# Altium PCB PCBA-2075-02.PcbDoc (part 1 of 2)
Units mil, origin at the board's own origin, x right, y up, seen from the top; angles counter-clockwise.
Board outline 4700 x 3550 mil, 4 copper layers (Top Layer, Signal Layer 1, Signal Layer 2, Bottom Layer), stack 65.3 mil thick; 129 components, 149 nets, 748 pads, 314 vias.
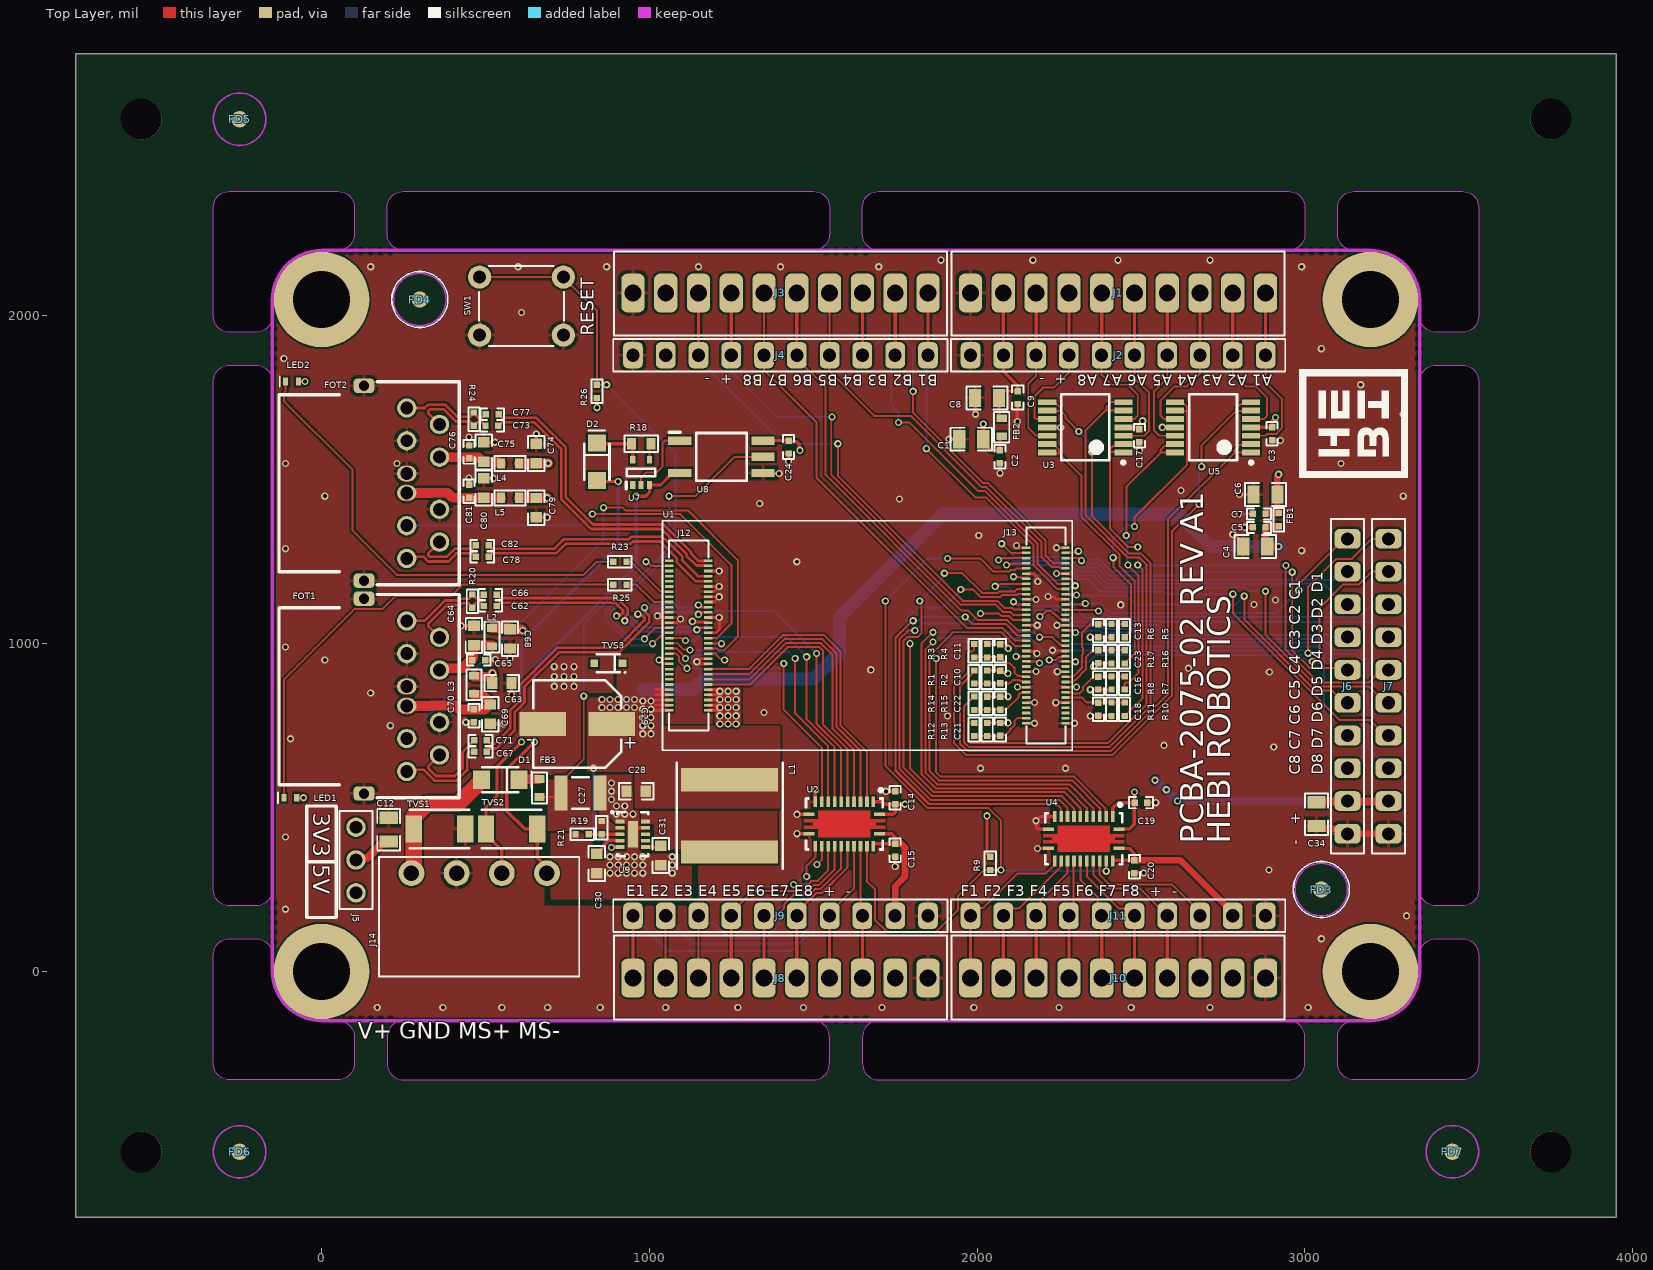
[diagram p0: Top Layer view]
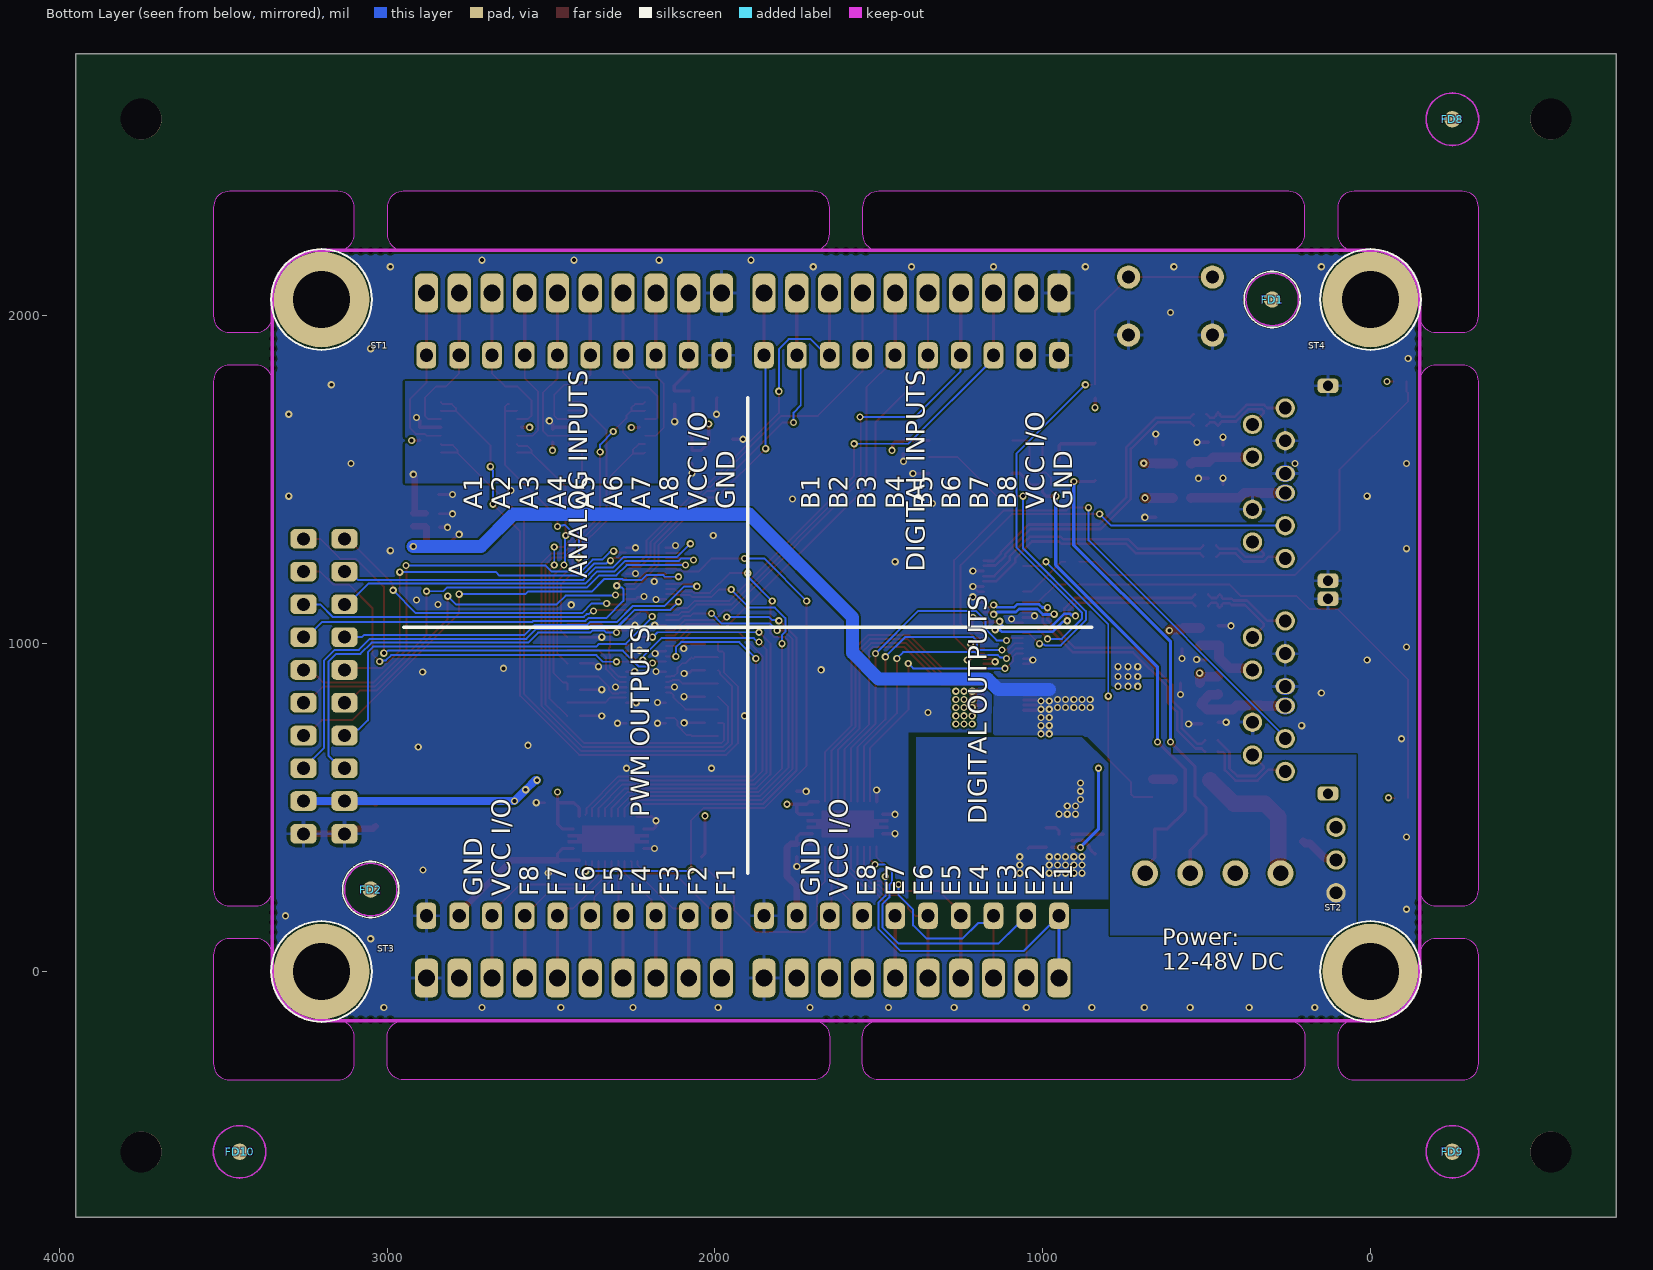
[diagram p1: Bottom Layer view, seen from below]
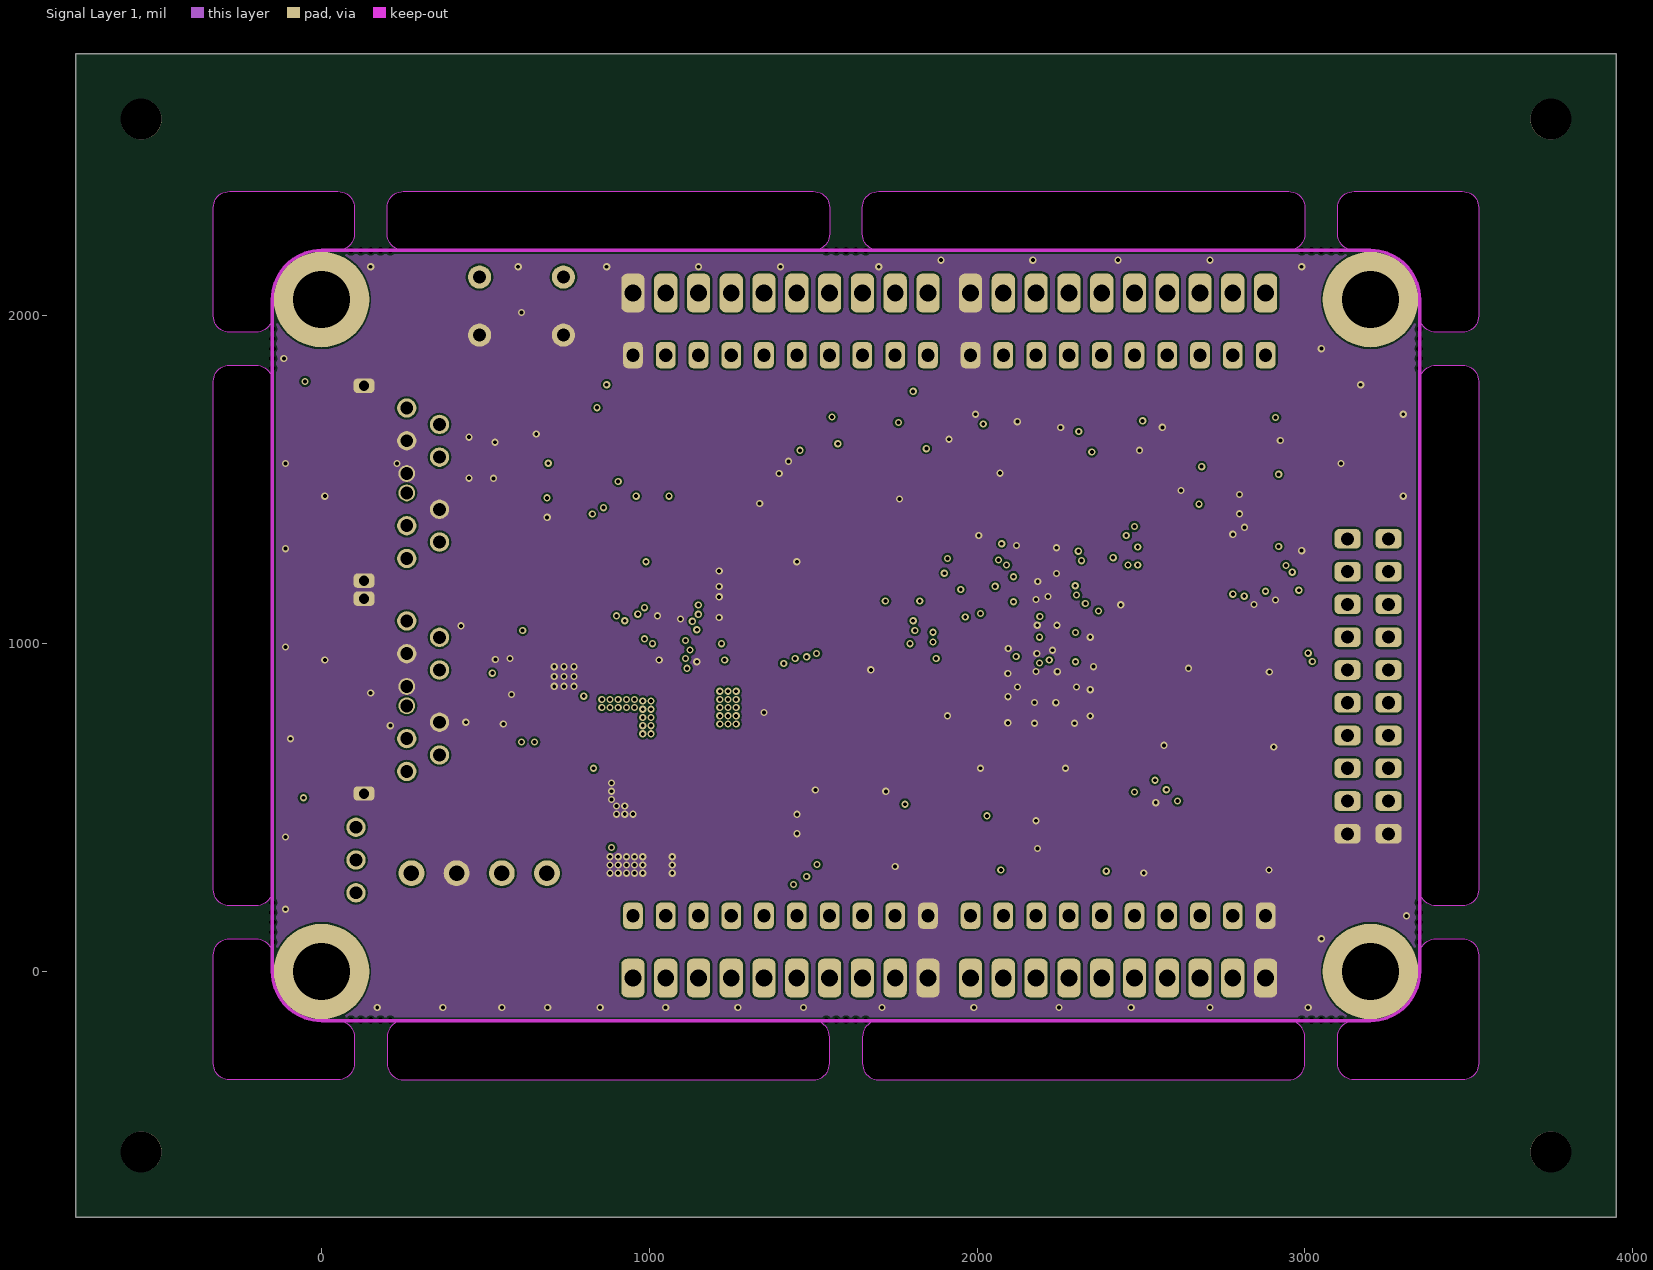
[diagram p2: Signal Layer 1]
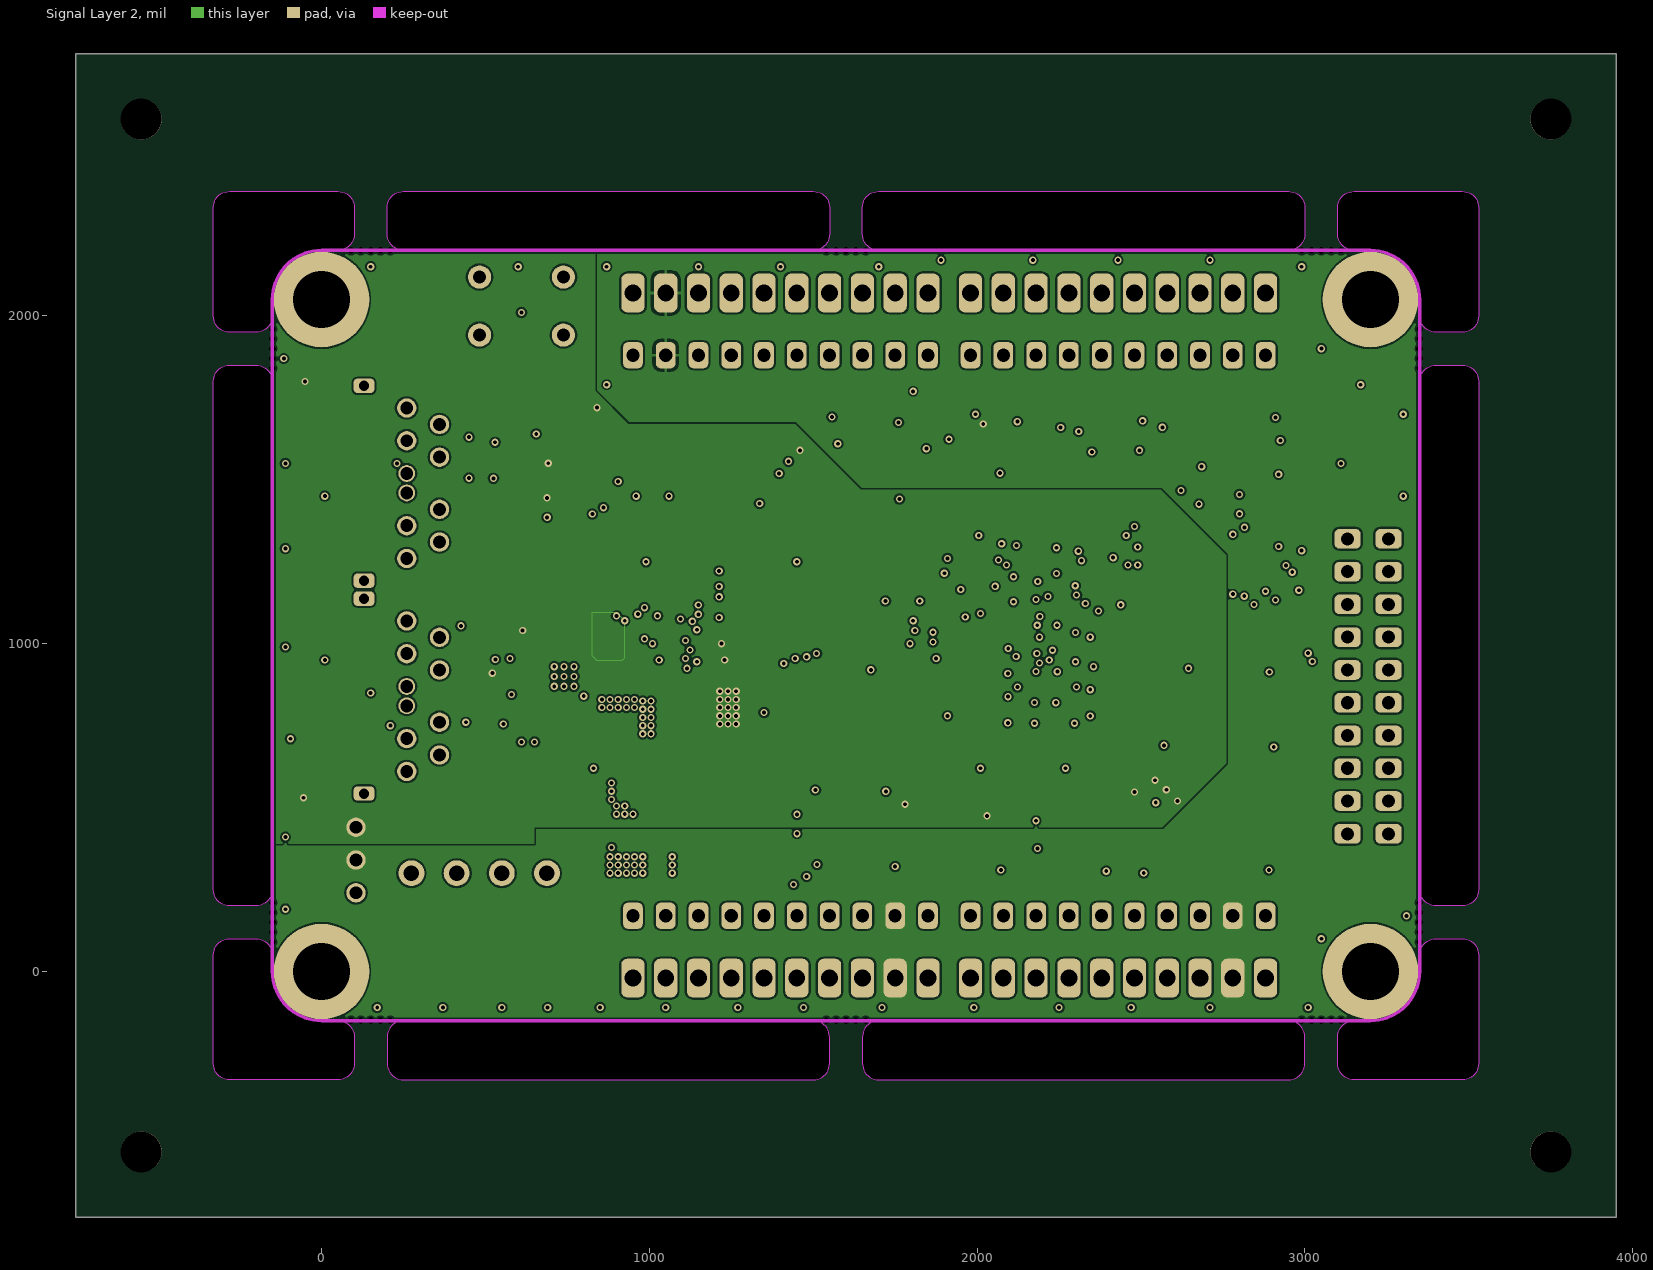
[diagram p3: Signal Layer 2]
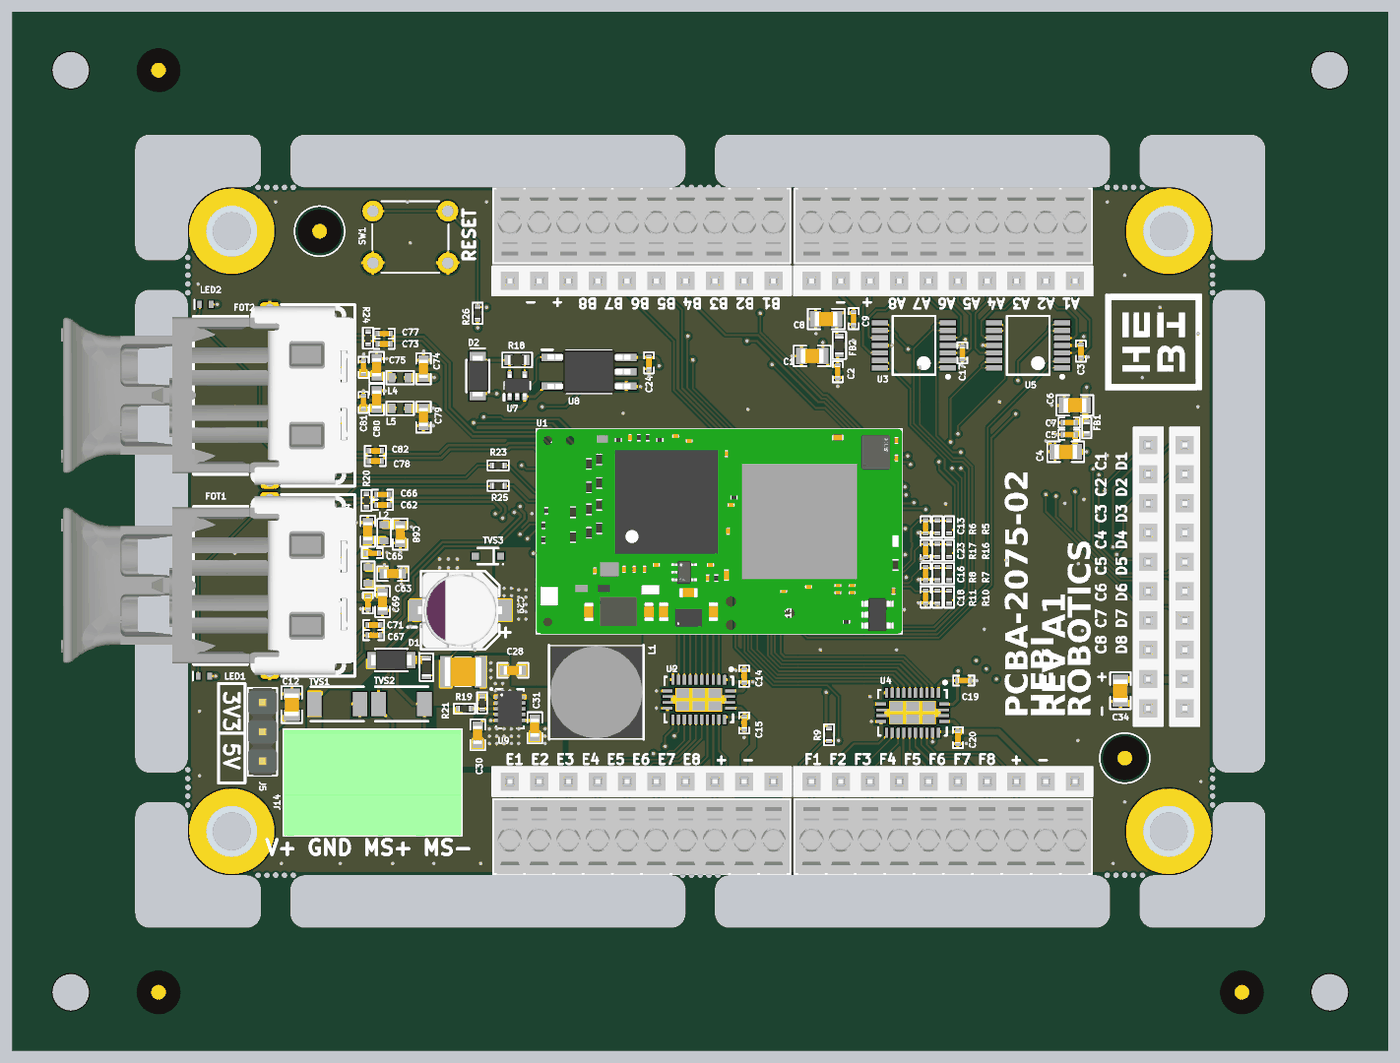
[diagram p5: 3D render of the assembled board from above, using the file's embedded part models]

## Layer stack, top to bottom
Top Solder: solder mask 0.4, Solder Resist, Dk 3.5
Top Layer: signal copper 1.7
Dielectric 1: core 7.9, FR-4, Dk 4.2
Signal Layer 1: signal copper 1.4
Dielectric 4: prepreg 43.3, Dk 4.2
Signal Layer 2: signal copper 1.4
Dielectric 2: core 7.9, Dk 4.2
Bottom Layer: signal copper 1.7
Bottom Solder: solder mask 0.4, Solder Resist, Dk 3.5

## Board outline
-750,-750 3950,-750 3950,2800 -750,2800
cut-out: 3100,-280 3100,-200 cw(c3150,-200) 3150,-150 3200,-150 ccw(c3200,0) 3350,0 3350,50 cw(c3400,50) 3400,100 3480,100 cw(c3480,50) 3530,50 3530,-280 cw(c3480,-280) 3480,-330 3150,-330 cw(c3150,-280)
cut-out: -280,100 -200,100 cw(c-200,50) -150,50 -150,0 ccw(c0,0) 0,-150 50,-150 cw(c50,-200) 100,-200 100,-280 cw(c50,-280) 50,-330 -280,-330 cw(c-280,-280) -330,-280 -330,50 cw(c-280,50)
cut-out: 200,-280 ccw(c250,-280) 250,-330 1500,-330 ccw(c1500,-280) 1550,-280 1550,-200 ccw(c1500,-200) 1500,-150 250,-150 ccw(c250,-200) 200,-200
cut-out: 1650,-280 ccw(c1700,-280) 1700,-330 2950,-330 ccw(c2950,-280) 3000,-280 3000,-200 ccw(c2950,-200) 2950,-150 1700,-150 ccw(c1700,-200) 1650,-200
cut-out: 3350,250 3350,1800 cw(c3400,1800) 3400,1850 3480,1850 cw(c3480,1800) 3530,1800 3530,250 cw(c3480,250) 3480,200 3400,200 cw(c3400,250)
cut-out: 1700,2200 cw(c1700,2250) 1650,2250 1650,2330 cw(c1700,2330) 1700,2380 2950,2380 cw(c2950,2330) 3000,2330 3000,2250 cw(c2950,2250) 2950,2200
cut-out: 200,2250 200,2330 cw(c250,2330) 250,2380 1500,2380 cw(c1500,2330) 1550,2330 1550,2250 cw(c1500,2250) 1500,2200 250,2200 cw(c250,2250)
cut-out: -280,200 cw(c-280,250) -330,250 -330,1800 cw(c-280,1800) -280,1850 -200,1850 cw(c-200,1800) -150,1800 -150,250 cw(c-200,250) -200,200
cut-out: 3480,1950 3400,1950 cw(c3400,2000) 3350,2000 3350,2050 ccw(c3200,2050) 3200,2200 3150,2200 cw(c3150,2250) 3100,2250 3100,2330 cw(c3150,2330) 3150,2380 3480,2380 cw(c3480,2330) 3530,2330 3530,2000 cw(c3480,2000)
cut-out: 100,2330 100,2250 cw(c50,2250) 50,2200 0,2200 ccw(c0,2050) -150,2050 -150,2000 cw(c-200,2000) -200,1950 -280,1950 cw(c-280,2000) -330,2000 -330,2330 cw(c-280,2330) -280,2380 50,2380 cw(c50,2330)

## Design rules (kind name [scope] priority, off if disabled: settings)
Clearance [All] p1: gap=6 ignorepadtopadclearanceinfootprint=FALSE
ComponentClearance ComponentClearance_3 [All vs IsNoBOMComponent] p1: gap=0 collisioncheckmode=3 verticalgap=0 showdistances=FALSE
ComponentClearance ComponentClearance_2 [HasFootprint('ARJM11C7-AB') vs HasFootprint('39-30-1020')] p2: gap=-10000 collisioncheckmode=3 verticalgap=100000 showdistances=FALSE
ComponentClearance ComponentClearance_1 [HasFootprint('ARJM11C7-AB') vs HasFootprint('ARJM11C7-AB')] p3: gap=-10000 collisioncheckmode=3 verticalgap=100000 showdistances=FALSE
ComponentClearance [All] p4: gap=10 collisioncheckmode=3 verticalgap=10 showdistances=FALSE
DiffPairsRouting [All] p1: maxlimit=10 minlimit=6 mostfreqgap=6 toplayer_minwidth=8 toplayer_maxwidth=15 toplayer_prefwidth=8 midlayer1_minwidth=8 midlayer1_maxwidth=15 midlayer1_prefwidth=8 midlayer2_minwidth=8 midlayer2_maxwidth=15 midlayer2_prefwidth=8 bottomlayer_minwidth=8 bottomlayer_maxwidth=15 bottomlayer_prefwidth=8 substack1={6BA4272A-E36A-4244-B1C5-CEF2182E9F2F} toplayer_{6ba4272a-e36a-4244-b1c5-cef2182e9f2f}_minwidth=15 toplayer_{6ba4272a-e36a-4244-b1c5-cef2182e9f2f}_maxwidth=15 toplayer_{6ba4272a-e36a-4244-b1c5-cef2182e9f2f}_prefwidth=15 midlayer1_{6ba4272a-e36a-4244-b1c5-cef2182e9f2f}_minwidth=15 midlayer1_{6ba4272a-e36a-4244-b1c5-cef2182e9f2f}_maxwidth=15 midlayer1_{6ba4272a-e36a-4244-b1c5-cef2182e9f2f}_prefwidth=15 midlayer2_{6ba4272a-e36a-4244-b1c5-cef2182e9f2f}_minwidth=15 midlayer2_{6ba4272a-e36a-4244-b1c5-cef2182e9f2f}_maxwidth=15 midlayer2_{6ba4272a-e36a-4244-b1c5-cef2182e9f2f}_prefwidth=15 bottomlayer_{6ba4272a-e36a-4244-b1c5-cef2182e9f2f}_minwidth=15 bottomlayer_{6ba4272a-e36a-4244-b1c5-cef2182e9f2f}_maxwidth=15 bottomlayer_{6ba4272a-e36a-4244-b1c5-cef2182e9f2f}_prefwidth=15 substack2={BF52BF6C-AB74-4071-B511-A36AC5A0F64E} toplayer_{bf52bf6c-ab74-4071-b511-a36ac5a0f64e}_minwidth=15 toplayer_{bf52bf6c-ab74-4071-b511-a36ac5a0f64e}_maxwidth=15 toplayer_{bf52bf6c-ab74-4071-b511-a36ac5a0f64e}_prefwidth=15 midlayer1_{bf52bf6c-ab74-4071-b511-a36ac5a0f64e}_minwidth=15 midlayer1_{bf52bf6c-ab74-4071-b511-a36ac5a0f64e}_maxwidth=15 midlayer1_{bf52bf6c-ab74-4071-b511-a36ac5a0f64e}_prefwidth=15 midlayer2_{bf52bf6c-ab74-4071-b511-a36ac5a0f64e}_minwidth=15 midlayer2_{bf52bf6c-ab74-4071-b511-a36ac5a0f64e}_maxwidth=15 midlayer2_{bf52bf6c-ab74-4071-b511-a36ac5a0f64e}_prefwidth=15 bottomlayer_{bf52bf6c-ab74-4071-b511-a36ac5a0f64e}_minwidth=15 bottomlayer_{bf52bf6c-ab74-4071-b511-a36ac5a0f64e}_maxwidth=15 bottomlayer_{bf52bf6c-ab74-4071-b511-a36ac5a0f64e}_prefwidth=15 substack3={B0BE1522-C43A-4A1D-8C74-4FD47ECCD6AD} toplayer_{b0be1522-c43a-4a1d-8c74-4fd47eccd6ad}_minwidth=15 toplayer_{b0be1522-c43a-4a1d-8c74-4fd47eccd6ad}_maxwidth=15 toplayer_{b0be1522-c43a-4a1d-8c74-4fd47eccd6ad}_prefwidth=15 midlayer1_{b0be1522-c43a-4a1d-8c74-4fd47eccd6ad}_minwidth=15 midlayer1_{b0be1522-c43a-4a1d-8c74-4fd47eccd6ad}_maxwidth=15 midlayer1_{b0be1522-c43a-4a1d-8c74-4fd47eccd6ad}_prefwidth=15 midlayer2_{b0be1522-c43a-4a1d-8c74-4fd47eccd6ad}_minwidth=15 midlayer2_{b0be1522-c43a-4a1d-8c74-4fd47eccd6ad}_maxwidth=15 midlayer2_{b0be1522-c43a-4a1d-8c74-4fd47eccd6ad}_prefwidth=15 bottomlayer_{b0be1522-c43a-4a1d-8c74-4fd47eccd6ad}_minwidth=15 bottomlayer_{b0be1522-c43a-4a1d-8c74-4fd47eccd6ad}_maxwidth=15 bottomlayer_{b0be1522-c43a-4a1d-8c74-4fd47eccd6ad}_prefwidth=15 maxuncoupledlength=500
Height [All] p1: minheight=0 maxheight=2000 prefheight=500
HoleSize [All] p1: absolutevalues=TRUE maxlimit=1000 minlimit=1 maxpercent=80.000 minpercent=20.000
HoleToHoleClearance HoleToHoleClearance_1 [HasFootprint('PJ-037A') vs HasFootprint('PJ-037A')] p1: gap=0 allowstackedmicrovias=TRUE
HoleToHoleClearance [All] p2: gap=10 allowstackedmicrovias=TRUE
MinimumSolderMaskSliver [All] p1 off: minsoldermaskwidth=10
PolygonConnect PolygonConnect_1 [All vs IsNamedPolygon('NO_THERMAL')] p1: connectstyle=Direct reliefconductorwidth=10 reliefentries=4 polygonreliefangle="90 Angle" airgapwidth=10
PolygonConnect [All] p2: thpad.connectstyle=Relief thpad.reliefconductorwidth=10 thpad.reliefentries=4 thpad.polygonreliefangle="90 Angle" thpad.airgapwidth=10 smdpad.connectstyle=Relief smdpad.reliefconductorwidth=10 smdpad.reliefentries=4 smdpad.polygonreliefangle="90 Angle" smdpad.airgapwidth=10 via.connectstyle=Direct via.reliefconductorwidth=10 via.reliefentries=4 via.polygonreliefangle="90 Angle" via.airgapwidth=10
RoutingVias [All] p1: holewidth=12 width=22 viastyle="Through Hole" minholewidth=12 minwidth=22 maxholewidth=40 maxwidth=100
SilkToSilkClearance [All] p1 off: silktosilkclearance=10
SilkToSolderMaskClearance [IsPad] p1 off: minsilkscreentomaskgap=10 clearancetoexposedcopper=TRUE
SolderMaskExpansion "Via Tenting" [IsVia] p1: expansion=2 istentingtop=TRUE
SolderMaskExpansion SolderMaskExpansion_1 [All] p2: expansion=4 istentingtop=FALSE
Width [All] p1: maxlimit=200 minlimit=6 preferedwidth=6 substack1={6BA4272A-E36A-4244-B1C5-CEF2182E9F2F} substack2={BF52BF6C-AB74-4071-B511-A36AC5A0F64E} substack3={B0BE1522-C43A-4A1D-8C74-4FD47ECCD6AD}
22 further rules are at their usual default settings.

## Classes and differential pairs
component class PCBA-2075-02: C24 C27 C28 C29 C30 C31 C62 C63 C64 C65 C66 C67 C68 C69 C70 C71 C73 C74 C75 C76 C77 C78 C79 C80 C81 C82 D1 D2 FB3 FD1 FD2 FD3 FD4 FD5 FD6 FD7 FD8 FD9 FD10 FOT1 FOT2 J12 J13 J14 L1 L2 L3 L4 L5 LED1 LED2 R18 R19 R20 R21 R23 R24 R25 R26 ST1 ST2 ST3 ST4 SW1 TVS1 TVS2 TVS3 U5 U7 U8 U9
component class io_connectors: C1 C2 C3 C4 C5 C6 C7 C8 C9 C10 C11 C12 C13 C14 C15 C16 C17 C18 C19 C20 C21 C22 C23 C34 FB1 FB2 J1 J2 J3 J4 J5 J6 J7 J8 J9 J10 J11 R1 R2 R3 R4 R5 R6 R7 R8 R9 R10 R11 R12 R13 R14 R15 R16 R17 U2 U3 U4 U5
differential pair TX2A: +TX2A_P -TX2A_N
differential pair TX1A: +TX1A_P -TX1A_N
differential pair RX2A: +RX2A_P -RX2A_N
differential pair RX1A: +RX1A_P -RX1A_N
differential pair TX2: +TX2_P -TX2_N
differential pair TX1: +TX1_P -TX1_N
differential pair RX2: +RX2_P -RX2_N
differential pair RX1: +RX1_P -RX1_N

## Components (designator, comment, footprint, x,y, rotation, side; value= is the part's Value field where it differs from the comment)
C1 "C-10uf-X5R-25V-10%-0805" C0805 1982.28,1623.79 r0 top
C2 "C-0.1uf-X7R-25V-10%-0402" C0402 2069.69,1570 r270 top
C3 "C-0.1uf-X7R-25V-10%-0402" C0402 2900,1640 r270 top
C4 "C-10uf-X5R-25V-10%-0805" C0805 2848.58,1296.61 r0 top
C5 "C-0.1uf-X7R-25V-10%-0402" C0402 2860,1355 r180 top
C6 "C-10uf-X5R-25V-10%-0805" C0805 2879.69,1455 r0 top
C7 "C-0.1uf-X7R-25V-10%-0402" C0402 2860,1396.17 r180 top
C8 "C-10uf-X5R-25V-10%-0805" C0805 2030,1750 r0 top
C9 "C-0.1uf-X7R-25V-10%-0402" C0402 2124,1751 r90 top
C10 "C-10000pf-X7R-50V-10%-0402" C0402 2070.63,898.39 r270 top
C11 "C-10000pf-X7R-50V-10%-0402" C0402 2070.63,978.39 r270 top
C12 "C-10uf-X5R-25V-10%-0805" C0805 205,432.72 r270 top
C13 "C-10000pf-X7R-50V-10%-0402" C0402 2370,1040 r90 top
C14 "C-0.1uf-X7R-25V-10%-0402" C0402 1750,530 r270 top
C15 "C-0.1uf-X7R-25V-10%-0402" C0402 1750,370 r90 top
C16 "C-10000pf-X7R-50V-10%-0402" C0402 2370,880 r90 top
C17 "C-0.1uf-X7R-25V-10%-0402" C0402 2495,1634.41 r270 top
C18 "C-10000pf-X7R-50V-10%-0402" C0402 2370,800 r90 top
C19 "C-0.1uf-X7R-25V-10%-0402" C0402 2500,515 r180 top
C20 "C-0.1uf-X7R-25V-10%-0402" C0402 2480,320 r90 top
C21 "C-10000pf-X7R-50V-10%-0402" C0402 2070.63,738.39 r270 top
C22 "C-10000pf-X7R-50V-10%-0402" C0402 2070.63,818.39 r270 top
C23 "C-10000pf-X7R-50V-10%-0402" C0402 2370,960 r90 top
C24 "CMP-00040-11" C0402 1425,1600 r270 top
C27 "C-4.7uf-X7S-100V-20%-1210" C1210 790,545 r180 top
C28 "C-10uf-X5R-16V-10%-0603" C0603 960,550 r0 top
C29 "16SVPC100M" CAPAE127P600-8N 780,755 r180 top locked
C30 "C-1uf-X7R-25V-10%-0603" C0603 840,329.53 r270 top
C31 "C-1uf-X7R-25V-10%-0603" C0603 1035,353.73 r270 top
C34 "C-10uf-X5R-25V-10%-0805" C0805 3035,480 r90 top
C62 "CMP-00040-11" C0402 515,1115 r180 top
C63 "C-10uf-X5R-16V-10%-0603" C0603 550,880 r180 top
C64 "C-10uf-X5R-16V-10%-0603" C0603 465,1025 r270 top
C65 "CMP-00040-11" C0402 480,950 r180 top
C66 "CMP-00040-11" C0402 515,1150 r180 top
C67 "CMP-00040-11" C0402 485,670 r180 top
C68 "C-10uf-X5R-16V-10%-0603" C0603 575,1015 r90 top
C69 "C-10uf-X5R-16V-10%-0603" C0603 515,785 r90 top
C70 "CMP-00040-11" C0402 465,780 r270 top
C71 "CMP-00040-11" C0402 485,705 r180 top
C73 "CMP-00040-11" C0402 520,1665 r0 top
C74 "C-10uf-X5R-16V-10%-0603" C0603 655,1580 r270 top
C75 "C-10uf-X5R-16V-10%-0603" C0603 495,1585 r270 top
C76 "CMP-00040-11" C0402 450,1585 r270 top
C77 "CMP-00040-11" C0402 520.31,1700 r0 top
C78 "CMP-00040-11" C0402 490,1265 r0 top
C79 "C-10uf-X5R-16V-10%-0603" C0603 655,1415 r90 top
C80 "C-10uf-X5R-16V-10%-0603" C0603 495,1475 r270 top
C81 "CMP-00040-11" C0402 450,1465 r90 top
C82 "CMP-00040-11" C0402 490.31,1300 r0 top
D1 "STPS2H100ZFY" SOD123F_ST 545,585 r180 top
D2 "STPS2H100ZFY" SOD123F_ST 840,1555 r270 top
FB1 "MMZ1005A222ET000" FB0402 2920,1378.35 r90 top
FB2 "MPZ1608S331ATD25" FB0603 2075,1660.18 r90 top
FB3 "MPZ1608S331ATD25" FB0603 665,560 r270 top
FD1 "FIDUCIAL" fiducial_01 300,2050 r180 bottom
FD2 "FIDUCIAL" fiducial_01 3050,250 r180 bottom
FD3 "FIDUCIAL" fiducial_01 3050,250 r0 top
FD4 "FIDUCIAL" fiducial_01 300,2050 r0 top
FD5 "*" fiducial_01_no_overlay -250,2600 r0 top
FD6 "*" fiducial_01_no_overlay -250,-550 r0 top
FD7 "*" fiducial_01_no_overlay 3450,-550 r0 top
FD8 "*" fiducial_01_no_overlay -250,2600 r180 bottom
FD9 "*" fiducial_01_no_overlay -250,-550 r180 bottom
FD10 "*" fiducial_01_no_overlay 3450,-550 r180 bottom
FOT1 "FB2M5KVR" OPTOLOCK 260,840 r180 top locked
FOT2 "FB2M5KVR" OPTOLOCK 260,1489.53 r180 top locked
J1 "OSTVN10A150" OSTVN10A150 2430,2070 r180 top locked
J2 "PPTC101LFBN-RC" PPTC101LFBN-RC 2430,1880 r180 top locked
J3 "OSTVN10A150" OSTVN10A150 1400,2070 r180 top locked
J4 "PPTC101LFBN-RC" PPTC101LFBN-RC 1400,1880 r180 top locked
J5 "M20-9990345" M20-9990345 105,340 r90 top
J6 "PPTC101LFBN-RC" PPTC101LFBN-RC 3130,870 r270 top
J7 "PPTC101LFBN-RC" PPTC101LFBN-RC 3255,870 r270 top
J8 "OSTVN10A150" OSTVN10A150 1400,-20 r0 top locked
J9 "PPTC101LFBN-RC" PPTC101LFBN-RC 1400,170 r0 top locked
J10 "OSTVN10A150" OSTVN10A150 2430,-20 r0 top locked
J11 "PPTC101LFBN-RC" PPTC101LFBN-RC 2430,170 r0 top locked
J12 "DF40HC(3.0)-60DS-0.4V(51)" DF40HC(3.0)-60DS-0.4V(51) 1120,1025 r90 top locked
J13 "DF40HC(3.0)-70DS-0.4V(51)" DF40HC(3.0)-70DS-0.4V(51) 2210,1025 r90 top locked
J14 "1844236" 1844236 481.1,300 r0 top locked
L1 "NRS8040T220MJGJV" NR8040T220M 1245,475 r90 top
L2 "ASMPH-0603-1R0M-T" I0603 520,1020 r270 top
L3 "ASMPH-0603-1R0M-T" I0603 465,875 r270 top
L4 "ASMPH-0603-1R0M-T" I0603 575,1550 r180 top
L5 "ASMPH-0603-1R0M-T" I0603 575,1445 r180 top
LED1 "IN-S42ATG" IN-S42AT -95,530 r180 top
LED2 "IN-S42ATG" IN-S42AT -90,1800 r180 top
R1 "R-3.3k-0.1%-0.063w-0402" R0402 1990.63,898.39 r270 top
R2 "R-4.7k-0.1%-0.063w-0402" R0402 2030.63,898.39 r270 top
R3 "R-3.3k-0.1%-0.063w-0402" R0402 1990.63,978.39 r270 top
R4 "R-4.7k-0.1%-0.063w-0402" R0402 2030.63,978.39 r270 top
R5 "R-3.3k-0.1%-0.063w-0402" R0402 2450,1040 r90 top
R6 "R-4.7k-0.1%-0.063w-0402" R0402 2410,1040 r90 top
R7 "R-3.3k-0.1%-0.063w-0402" R0402 2450,880 r90 top
R8 "R-4.7k-0.1%-0.063w-0402" R0402 2410,880 r90 top
R9 "R-4.7k-1%-0.063w-0402" R0402 2040,330 r270 top
R10 "R-3.3k-0.1%-0.063w-0402" R0402 2450,800 r90 top
R11 "R-4.7k-0.1%-0.063w-0402" R0402 2410,800 r90 top
R12 "R-3.3k-0.1%-0.063w-0402" R0402 1990.63,738.39 r270 top
R13 "R-4.7k-0.1%-0.063w-0402" R0402 2030.63,738.39 r270 top
R14 "R-3.3k-0.1%-0.063w-0402" R0402 1990.63,818.39 r270 top
R15 "R-4.7k-0.1%-0.063w-0402" R0402 2030.63,818.21 r270 top
R16 "R-3.3k-0.1%-0.063w-0402" R0402 2450,960 r90 top
R17 "R-4.7k-0.1%-0.063w-0402" R0402 2410,960 r90 top
R18 "R-220-1%-0.25w-0603" R0603 975,1610 r180 top
R19 "R-3.3M-1%-0.063w-0402" R0402 855,438.73 r90 top
R20 "R-100-1%-0.063w-0402" R0402 460,1130 r90 top value=100
R21 "R-470k-1%-0.063w-0402" R0402 795,418.73 r180 top
R23 "R-1k-1%-0.063w-0402" R0402 910,1250 r180 top
R24 "R-100-1%-0.063w-0402" R0402 465,1685 r90 top value=100
R25 "R-1k-1%-0.063w-0402" R0402 910,1180 r180 top
R26 "R-10k-1%-0.063w-0402" R0402 840,1770 r270 top
ST1 "9774030960R" 9774030960R 3200,2050 r180 bottom locked
ST2 "9774030960R" 9774030960R 0,0 r180 bottom locked
ST3 "9774030960R" 9774030960R 3200,0 r180 bottom locked
ST4 "9774030960R" 9774030960R 0,2050 r180 bottom locked
SW1 "222ADVBA" 222ADVBA 610,2030 r0 top locked
TVS1 "SMAJ51CA" SMA_BI_BOURNS 360,435 r0 top
TVS2 "SMAJ51CA" SMA_BI_BOURNS 580,435 r0 top
TVS3 "PESD5V0S1UJ,115" SOD-323F_NXP 875,940 r180 top
U1 "IO-MICRO" IO-MICRO-Footprint-1 1665,1025 r0 top
U2 "SN74LVC8T245RHLR" R-PVQFN-N24_TI 1595,450 r270 top
U3 "TSV324IPT" TSSOP14_ST 2330,1660 r180 top
U4 "SN74LVC8T245RHLR" R-PVQFN-N24_TI 2325,405 r270 top
U5 "TSV324IPT" TSSOP14_ST 2720,1660 r180 top
U7 "PSSI2021SAY,115" PSSI2021SAY,115 975,1522.5 r90 top
U8 "ACPL-M21L-500E" SOT125P700X260-5N 1220,1570 r0 top
U9 "MAX17502FATB+T" 10_TDFN_MAXIM 950,418.73 r0 top

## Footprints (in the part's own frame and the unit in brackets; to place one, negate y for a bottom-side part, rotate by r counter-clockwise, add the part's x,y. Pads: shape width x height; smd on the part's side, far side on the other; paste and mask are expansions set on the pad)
10_TDFN_MAXIM [mm] "10 TDFN from Maxim MAX17502"
  rect 0.7x0.3 smd: 1(-0.99,1) 2(-0.99,0.5) 3(-0.99,0) 4(-0.99,-0.5) 5(-0.99,-1) 6(0.99,-1) 7(0.99,-0.5) 8(0.99,0) 9(0.99,0.5) 10(0.99,1)
  rect 0.8x2.08 smd: 11(0,0)
  silkscreen extent -1.65,-1.7 1.2,1.75, body extent -1.05,-1.55 1.05,1.55, height 0.8
222ADVBA [mm] "222ADVBA from CTS"
  round 1.8 hole 1: 1(-3.25,2.25) 1(3.25,2.25) 2(-3.25,-2.25) 2(3.25,-2.25)
  silkscreen extent -3.3,-3.1 3.3,3.1, body extent -3.25,-3 3.25,3, height 4.3
1844236 [mm] "TERM BLOCK HDR 4POS 90DEG 3.5MM, Pheonix Contact"
  round 2 hole 1.2: 1(-5.25,0) 2(-1.75,0) 3(1.75,0) 4(5.25,0)
  silkscreen extent -7.75,-8 7.75,1.25, body extent -7.7,-8 7.7,1.2, height 7.25
9774030960R [mm] "3mm SMD Spacer from Wurth"
  round 7.4 hole 4.4: 1(0,0)
  silkscreen extent -3.9,-3.9 3.9,3.9, body extent -3,-3 2.99,3, height 2.03
C0402 [mm] "Generic 0402 Capacitor"
  rect 0.5x0.5 smd: 1(-0.5,0) 2(0.5,0)
  silkscreen extent -0.91,-0.43 0.91,0.43, body extent -0.5,-0.25 0.5,0.25, height 0.55
C0603 [mm] "Generic 0603 Capacitor"
  rect 0.8x0.9 smd: 1(-0.75,0) 2(0.75,0)
  silkscreen extent -1.35,-0.64 1.35,0.64, body extent -0.8,-0.4 0.8,0.4, height 0.9
C0805 [mm] "Generic 0805 Capacitor"
  rect 0.95x1.4 smd: 1(-0.925,0) 2(0.925,0)
  silkscreen extent -1.6,-0.89 1.6,0.89, body extent -1,-0.63 1,0.63, height 1.4
C1210 [mm] "Generic 1210 capacitor"
  rect 1x2.7 smd: 1(-1.5,0) 2(1.5,0)
  silkscreen extent -0.65,-1.22 0.65,1.23, body extent -1.6,-1.25 1.6,1.25, height 2.8
CAPAE127P600-8N [mm]
  rect 3.6x1.85 smd: +(-2.675,0) -(2.675,0)
  silkscreen extent -3.4,-3.4 3.4,3.4, body extent -3.65,-3.3 3.65,3.3, height 5.94
DF40HC(3.0)-60DS-0.4V(51) [mm] "DF40HC(3.0)-60DS-0.4V(51)"
  rect 0.203x0.65 smd paste+0 mask+0: 1(5.8,-1.515) 2(5.8,1.515) 3(5.4,-1.515) 4(5.4,1.515) 5(5,-1.515) 6(5,1.515) 7(4.6,-1.515) 8(4.6,1.515) 9(4.2,-1.515) 10(4.2,1.515) 11(3.8,-1.515) 12(3.8,1.515) 13(3.4,-1.515) 14(3.4,1.515) 15(3,-1.515) 16(3,1.515) 17(2.6,-1.515) 18(2.6,1.515) 19(2.2,-1.515) 20(2.2,1.515) 21(1.8,-1.515) 22(1.8,1.515) 23(1.4,-1.515) 24(1.4,1.515) 25(1,-1.515) 26(1,1.515) 27(0.6,-1.515) 28(0.6,1.515) 29(0.2,-1.515) 30(0.2,1.515) 31(-0.2,-1.515) 32(-0.2,1.515) 33(-0.6,-1.515) 34(-0.6,1.515) 35(-1,-1.515) 36(-1,1.515) 37(-1.4,-1.515) 38(-1.4,1.515) 39(-1.8,-1.515) 40(-1.8,1.515) 41(-2.2,-1.515) 42(-2.2,1.515) 43(-2.6,-1.515) 44(-2.6,1.515) 45(-3,-1.515) 46(-3,1.515) 47(-3.4,-1.515) 48(-3.4,1.515) 49(-3.8,-1.515) 50(-3.8,1.515) 51(-4.2,-1.515) 52(-4.2,1.515) 53(-4.6,-1.515) 54(-4.6,1.515) 55(-5,-1.515) 56(-5,1.515) 57(-5.4,-1.515) 58(-5.4,1.515) 59(-5.8,-1.515) 60(-5.8,1.515)
  silkscreen extent -7.38,-1.52 7.38,1.52, body extent -7.3,-1.69 7.3,1.69, height 2.9
DF40HC(3.0)-70DS-0.4V(51) [mm] "3mm height DF40, 70pin Hirose"
  rect 0.203x0.65 smd paste+0 mask+0: 1(6.8,-1.515) 2(6.8,1.515) 3(6.4,-1.515) 4(6.4,1.515) 5(6,-1.515) 6(6,1.515) 7(5.6,-1.515) 8(5.6,1.515) 9(5.2,-1.515) 10(5.2,1.515) 11(4.8,-1.515) 12(4.8,1.515) 13(4.4,-1.515) 14(4.4,1.515) 15(4,-1.515) 16(4,1.515) 17(3.6,-1.515) 18(3.6,1.515) 19(3.2,-1.515) 20(3.2,1.515) 21(2.8,-1.515) 22(2.8,1.515) 23(2.4,-1.515) 24(2.4,1.515) 25(2,-1.515) 26(2,1.515) 27(1.6,-1.515) 28(1.6,1.515) 29(1.2,-1.515) 30(1.2,1.515) 31(0.8,-1.515) 32(0.8,1.515) 33(0.4,-1.515) 34(0.4,1.515) 35(0,-1.515) 36(0,1.515) 37(-0.4,-1.515) 38(-0.4,1.515) 39(-0.8,-1.515) 40(-0.8,1.515) 41(-1.2,-1.515) 42(-1.2,1.515) 43(-1.6,-1.515) 44(-1.6,1.515) 45(-2,-1.515) 46(-2,1.515) 47(-2.4,-1.515) 48(-2.4,1.515) 49(-2.8,-1.515) 50(-2.8,1.515) 51(-3.2,-1.515) 52(-3.2,1.515) 53(-3.6,-1.515) 54(-3.6,1.515) 55(-4,-1.515) 56(-4,1.515) 57(-4.4,-1.515) 58(-4.4,1.515) 59(-4.8,-1.515) 60(-4.8,1.515) 61(-5.2,-1.515) 62(-5.2,1.515) 63(-5.6,-1.515) 64(-5.6,1.515) 65(-6,-1.515) 66(-6,1.515) 67(-6.4,-1.515) 68(-6.4,1.515) 69(-6.8,-1.515) 70(-6.8,1.515)
  silkscreen extent -8.38,-1.52 8.38,1.52, body extent -8.3,-1.69 8.3,1.69, height 2.9
FB0402 [mm] "Chip Ferrite Bead 2-Leads, Body 1.0x0.5mm, based on Panasonic datasheet"
  rect 0.475x0.5 smd: 1(-0.513,0) 2(0.512,0)
  silkscreen extent -0.9,-0.4 0.9,0.4, body extent -0.5,-0.28 0.5,0.28, height 0.55
FB0603 [mm] "Based on TDK datasheet for MMZ Series"
  rect 0.6x0.8 smd: 1(-0.7,0) 2(0.7,0)
  silkscreen extent -1.19,-0.58 1.19,0.58, body extent -0.8,-0.4 0.8,0.4, height 0.8
fiducial_01 [mil] "fiducial"
  round 50 smd paste-100 mask+50: F(0,0)
  Top Layer keep-out circle w5: c0,0 r80
  silkscreen extent -86,-85 86,85
fiducial_01_no_overlay [mil] "fiducial"
  round 50 smd paste-100 mask+50: F(0,0)
  Top Layer keep-out circle w5: c0,0 r80
I0603 [mm] "Based on TDK datasheet for MMZ Series"
  rect 0.6x0.8 smd: 1(-0.7,0) 2(0.7,0)
  silkscreen extent -1.19,-0.58 1.19,0.58, body extent -0.88,-0.48 0.87,0.48, height 0.95
IN-S42AT [mm] "single 0402 LED 0.35mm height based on IN-S42AT"
  rect 0.4x0.6 smd: A(-0.5,0) C(0.5,0)
  silkscreen extent 0.95,-0.4 0.95,0.4, body extent -0.5,-0.25 0.5,0.25, height 0.35
IO-MICRO-Footprint-1 [mil]
  rect 4x4 smd paste-1000 mask+0: A1(604.65,267.72) A2(485.35,267.72) A3(604.65,251.97) A4(485.35,251.97) A5(604.65,236.22) A6(485.35,236.22) A7(604.65,220.47) A8(485.35,220.47) A9(604.65,204.72) A10(485.35,204.72) A11(604.65,188.98) A12(485.35,188.98) A13(604.65,173.23) A14(485.35,173.23) A15(604.65,157.48) A16(485.35,157.48) A17(604.65,141.73) A18(485.35,141.73) A19(604.65,125.98) A20(485.35,125.98) A21(604.65,110.24) A22(485.35,110.24) A23(604.65,94.49) A24(485.35,94.49) A25(604.65,78.74) A26(485.35,78.74) A27(604.65,62.99) A28(485.35,62.99) A29(604.65,47.24) A30(485.35,47.24) A31(604.65,31.5) A32(485.35,31.5) A33(604.65,15.75) A34(485.35,15.75) A35(604.65,0) A36(485.35,0) A37(604.65,-15.75) A38(485.35,-15.75) A39(604.65,-31.5) A40(485.35,-31.5) A41(604.65,-47.24) A42(485.35,-47.24) A43(604.65,-62.99) A44(485.35,-62.99) A45(604.65,-78.74) A46(485.35,-78.74) A47(604.65,-94.49) A48(485.35,-94.49) A49(604.65,-110.24) A50(485.35,-110.24) A51(604.65,-125.98) A52(485.35,-125.98) A53(604.65,-141.73) A54(485.35,-141.73) A55(604.65,-157.48) A56(485.35,-157.48) A57(604.65,-173.23) A58(485.35,-173.23) A59(604.65,-188.98) A60(485.35,-188.98) A61(604.65,-204.72) A62(485.35,-204.72) A63(604.65,-220.47) A64(485.35,-220.47) A65(604.65,-236.22) A66(485.35,-236.22) A67(604.65,-251.97) A68(485.35,-251.97) A69(604.65,-267.72) A70(485.35,-267.72) B1(-485.35,228.35) B2(-604.65,228.35) B3(-485.35,212.6) B4(-604.65,212.6) B5(-485.35,196.85) B6(-604.65,196.85) B7(-485.35,181.1) B8(-604.65,181.1) B9(-485.35,165.35) B10(-604.65,165.35) B11(-485.35,149.61) B12(-604.65,149.61) B13(-485.35,133.86) B14(-604.65,133.86) B15(-485.35,118.11) B16(-604.65,118.11) B17(-485.35,102.36) B18(-604.65,102.36) B19(-485.35,86.61) B20(-604.65,86.61) B21(-485.35,70.87) B22(-604.65,70.87) B23(-485.35,55.12) B24(-604.65,55.12) B25(-485.35,39.37) B26(-604.65,39.37) B27(-485.35,23.62) B28(-604.65,23.62) B29(-485.35,7.87) B30(-604.65,7.87) B31(-485.35,-7.87) B32(-604.65,-7.87) B33(-485.35,-23.62) B34(-604.65,-23.62) B35(-485.35,-39.37) B36(-604.65,-39.37) B37(-485.35,-55.12) B38(-604.65,-55.12) B39(-485.35,-70.87) B40(-604.65,-70.87) B41(-485.35,-86.61) B42(-604.65,-86.61) B43(-485.35,-102.36) B44(-604.65,-102.36) B45(-485.35,-118.11) B46(-604.65,-118.11) B47(-485.35,-133.86) B48(-604.65,-133.86) B49(-485.35,-149.61) B50(-604.65,-149.61) B51(-485.35,-165.35) B52(-604.65,-165.35) B53(-485.35,-181.1) B54(-604.65,-181.1) B55(-485.35,-196.85) B56(-604.65,-196.85) B57(-485.35,-212.6) B58(-604.65,-212.6) B59(-485.35,-228.35) B60(-604.65,-228.35)
  silkscreen extent -605,-330 605,330, body extent -625,-350 625,350, height 212
M20-9990345 [mil] "Harwin 3 pin header"
  round 59 hole 39: 1(-100,0) 2(0,0) 3(100,0)
  silkscreen extent -150,-50 150,50, body extent -150,-50 150,50, height 341
NR8040T220M [mm] "Taiyo Yuden NR8040T220M"
  rect 1.8x7.5 smd: 1(-2.8,0) 2(2.8,0)
  silkscreen extent -4.1,-4.1 4.1,4.1, body extent -4.1,-4 4.1,4, height 4.1
OPTOLOCK [mm] "OptoLock FOT from Firefomms"
  rrect50% 1.6x1.1 hole 0.8: 1(3.31,-7.55) 12(3.31,7.55)
  round 1.5 hole 1: 2(0,-5.83) 3(-2.54,-4.56) 4(0,-3.29) 5(-2.54,-2.02) 8(-2.54,2.02) 9(0,3.29) 10(-2.54,4.56) 11(0,5.83)
  round 1.025 / inner round 1.3 / far side round 1.025 hole 1 mask+0.102: 6(0,-0.752) 7(0,0.752)
  oval 1.5x1.2 smd: 6(0,-0.752) 7(0,0.752)
  oval 1.5x1.2 smd far side: 6(0,-0.752) 7(0,0.752)
  Top Layer region: -0.283,-0.167 0,-0.102 0.283,-0.167 0.283,-0.167 0.283,-0.167 0.524,-0.283 0.691,-0.491 0.75,-0.752 0.691,-1.012 0.524,-1.221 0.283,-1.337 0.283,-1.337 0.283,-1.337 0,-1.402 -0.283,-1.337 -0.283,-1.337 -0.283,-1.337 -0.524,-1.221 -0.691,-1.012 -0.75,-0.752 -0.691,-0.491 -0.524,-0.283 -0.283,-0.167
  Top Layer region: -0.283,0.167 0,0.102 0.283,0.167 0.283,0.167 0.283,0.167 0.524,0.283 0.691,0.491 0.75,0.752 0.691,1.012 0.524,1.221 0.283,1.337 0.283,1.337 0.283,1.337 0,1.402 -0.283,1.337 -0.283,1.337 -0.283,1.337 -0.524,1.221 -0.691,1.012 -0.75,0.752 -0.691,0.491 -0.524,0.283 -0.283,0.167
  Bottom Layer region: -0.283,-0.167 0,-0.102 0.283,-0.167 0.283,-0.167 0.283,-0.167 0.524,-0.283 0.691,-0.491 0.75,-0.752 0.691,-1.012 0.524,-1.221 0.283,-1.337 0.283,-1.337 0.283,-1.337 0,-1.402 -0.283,-1.337 -0.283,-1.337 -0.283,-1.337 -0.524,-1.221 -0.691,-1.012 -0.75,-0.752 -0.691,-0.491 -0.524,-0.283 -0.283,-0.167
  Bottom Layer region: -0.283,0.167 0,0.102 0.283,0.167 0.283,0.167 0.283,0.167 0.524,0.283 0.691,0.491 0.75,0.752 0.691,1.012 0.524,1.221 0.283,1.337 0.283,1.337 0.283,1.337 0,1.402 -0.283,1.337 -0.283,1.337 -0.283,1.337 -0.524,1.221 -0.691,1.012 -0.75,0.752 -0.691,0.491 -0.524,0.283 -0.283,0.167
  silkscreen extent -4.06,-7.87 9.91,7.87, body extent -4.13,-7.75 21.41,7.75, height 11.85
OSTVN10A150 [mm] "10 pin 0.1 inch pitch screw terminal from on shore tech"
  rrect50% 1.8x3 hole 1.3: 1(-11.43,0) 2(-8.89,0) 3(-6.35,0) 4(-3.81,0) 5(-1.27,0) 6(1.27,0) 7(3.81,0) 8(6.35,0) 9(8.89,0) 10(11.43,0)
  silkscreen extent -12.9,-3.2 12.9,3.3, body extent -12.9,-3.22 12.9,3.28, height 8.5
PPTC101LFBN-RC [mil] "PPTC101LFBN-RC 10 pin 100 mil header from sullins"
  rrect50% 60x80 hole 40: 1(-450,0) 2(-350,0) 3(-250,0) 4(-150,0) 5(-50,0) 6(50,0) 7(150,0) 8(250,0) 9(350,0) 10(450,0)
  silkscreen extent -510,-50 510,50, body extent -510,-50 510,50, height 335
PSSI2021SAY,115 [mm] "SOT23, 5-Leads, Body 2.00x2.10mm, Pitch 0.65mm, IPC High Density"
  rect 0.6x0.4 smd: 1(-0.975,0.65) 2(-0.975,0) 3(-0.975,-0.65) 4(0.975,-0.65) 5(0.975,0.65)
  silkscreen extent -1.27,-1.1 0.3,1.14, body extent -1.15,-1.1 1.15,1.1, height 1.1
R0402 [mm] "Generic 0402 Resistor"
  rect 0.475x0.5 smd: 1(-0.513,0) 2(0.512,0)
  silkscreen extent -0.91,-0.43 0.91,0.43, body extent -0.5,-0.25 0.5,0.25, height 0.4
R0603 [mm] "Generic 0603 resistor"
  rect 0.7x0.9 smd: 1(-0.75,0) 2(0.75,0)
  silkscreen extent -1.3,-0.64 1.3,0.64, body extent -0.8,-0.4 0.8,0.4, height 0.55
R-PVQFN-N24_TI [mm] "R-PVQFN-N24 from TI sn74lvc8t245"
  rect 0.28x0.85 smd: 1(-0.75,2.725) 12(-0.75,-2.725) 13(0.75,-2.725) 24(0.75,2.725)
  rect 0.85x0.28 smd: 2(-1.725,2.25) 3(-1.725,1.75) 4(-1.725,1.25) 5(-1.725,0.75) 6(-1.725,0.25) 7(-1.725,-0.25) 8(-1.725,-0.75) 9(-1.725,-1.25) 10(-1.725,-1.75) 11(-1.725,-2.25) 14(1.725,-2.25) 15(1.725,-1.75) 16(1.725,-1.25) 17(1.725,-0.75) 18(1.725,-0.25) 19(1.725,0.25) 20(1.725,0.75) 21(1.725,1.25) 22(1.725,1.75) 23(1.725,2.25)
  Top Layer region: -0.365,3.15 -0.365,2.025 -1.025,2.025 -1.025,-2.025 -0.365,-2.025 -0.365,-3.15 -0.135,-3.15 -0.135,-2.425 0.135,-2.425 0.135,-3.15 0.365,-3.15 0.365,-2.025 1.025,-2.025 1.025,2.025 0.365,2.025 0.365,3.15 0.135,3.15 0.135,2.425 -0.135,2.425 -0.135,3.15
  silkscreen extent -2.75,-2.97 1.97,2.98, body extent -1.83,-2.82 1.83,2.83, height 1
SMA_BI_BOURNS [mm] "Bidirectional TVS BOURNS, SMA DO-214AC from SMAJ"
  rect 1.27x2.1 smd: A(1.985,0) C(-1.985,0)
  silkscreen extent -2.3,-1.5 2.3,1.5, body extent -2.28,-1.46 2.28,1.46, height 2.62
SOD123F_ST [mm] "SOD123Flat from ST  STPS2H100ZFY"
  rect 1.3x1.4 smd: A(1.45,0) C(-1.45,0)
  silkscreen extent -2.41,-0.98 1.4,0.98, body extent -1.75,-0.9 1.75,0.9, height 1.1
SOD-323F_NXP [mm] "Molded Diode, 2-Leads, Body 1.7x1.3mm, based on PESD5V0S1UJ datasheet"
  rect 0.6x0.6 smd: A(1.1,0) C(-1.1,0)
  silkscreen extent -1.35,-0.7 0.9,0.75, body extent -0.9,-0.67 0.9,0.67, height 0.8
SOT125P700X260-5N [mm] "SOT23, 5-Leads, Body 3.60x7.00mm, Pitch 1.25mm, IPC Medium Density"
  rect 1.8x0.64 smd: 1(-3.23,1.25) 3(-3.23,-1.25) 4(3.23,-1.25) 5(3.23,0) 6(3.23,1.25)
  silkscreen extent -4.06,-1.85 1.95,1.91, body extent -3.6,-1.85 3.6,1.85, height 2.6
TSSOP14_ST [mm] "TSSOP 14 pin from ST TSV324"
  rect 1.4x0.45 smd: 1(-2.95,1.95) 2(-2.95,1.3) 3(-2.95,0.65) 4(-2.95,0) 5(-2.95,-0.65) 6(-2.95,-1.3) 7(-2.95,-1.95) 8(2.95,-1.95) 9(2.95,-1.3) 10(2.95,-0.65) 11(2.95,0) 12(2.95,0.65) 13(2.95,1.3) 14(2.95,1.95)
  silkscreen extent -3.08,-2.55 1.85,2.85, body extent -2.25,-2.55 2.25,2.55, height 1.2

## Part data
C1 C4 C6 C8 C12 C34: library part CMP-00042-6, "Capacitor Ceramic 10uF 25V X5R 10% SMD 0805", Capacitance=10uF, Operating Temperature="-55°C ~ 85°C", Package / Case=0805, Temperature Coefficient=X5R, Tolerance=10%, Voltage - Rated=25V
C2 C3 C5 C7 C9 C14 C15 C17 C19 C20: library part CMP-00040-11, "Capacitor Ceramic 0.1uF 25V X7R 10% SMD 0402", Capacitance=0.1uF, Operating Temperature="-55°C ~ 125°C", Package / Case=0402, Temperature Coefficient=X7R, Tolerance=10%, Voltage - Rated=25V
C10 C11 C13 C16 C18 C21 C22 C23: library part CMP-00041-8, "Capacitor Ceramic 10000pF 50V X7R 10% SMD 0402", Capacitance=10000pF, Operating Temperature="-55°C ~ 125°C", Package / Case=0402, Temperature Coefficient=X7R, Tolerance=10%, Voltage - Rated=50V
C24 C62 C65 C66 C67 C70 C71 C73 C76 C77 C78 C81 C82: "Capacitor Ceramic 0.1uF 25V X7R 10% SMD 0402", Capacitance=0.1uF, Operating Temperature="-55°C ~ 125°C", Package / Case=0402, Temperature Coefficient=X7R, Tolerance=10%, Voltage - Rated=25V
C27: library part C-4.7uf-X7S-100V-20%-1210-6, "Capacitor Ceramic 4.7uF 100V X7S 20% SMD 1210", Capacitance=4.7uF, Operating Temperature="-55°C ~ 125°C", Package / Case=1210, Temperature Coefficient=X7S, Tolerance=±20%, Voltage - Rated=100V
C28 C63 C64 C68 C69 C74 C75 C79 C80: library part CMP-00102-2, "Capacitor Ceramic 10uF 16V X5R 10% SMD 0603", Capacitance=10uF, Operating Temperature="-55°C ~ 85°C", Package / Case=0603, Temperature Coefficient=X5R, Tolerance=10%, Voltage - Rated=16V
C29: library part CMP-00071-2, "CAP ALUM POLY 100UF 20% 16V SMD", Capacitance=100uF, Case/Package=Radial, ESR (Equivalent Series Resistance)=24mR, Leakage Current=300uA, Max Operating Temperature=105°C, Min Operating Temperature=-55°C, Package Quantity=1000, Ripple Current=2.49A, Tolerance=20%, Voltage=16V
C30 C31: library part CMP-00057-3, "Capacitor Ceramic 1uF 25V X7R 10% SMD 0603", Capacitance=1uF, Operating Temperature="-55°C ~ 125°C", Package / Case=0603, Temperature Coefficient=X7R, Tolerance=10%, Voltage - Rated=25V
D1 D2: library part CMP-698-0009-4, "DIODE SCHOTTKY 100V 2A SOD123F", Capacitance @ Vr, F=-, Current - Average Rectified (Io)=2A, Current - Reverse Leakage @ Vr="1µA @ 100V", Operating Temperature - Junction="-40°C ~ 175°C", Package / Case=SOD-123F, Voltage - DC Reverse (Vr) (Max)=100V, Voltage - Forward (Vf) (Max) @ If="960mV @ 4A"
FB1: library part CMP-00233-4, "FERRITE BEAD 2.2 KOHM 0402 1LN", Current Rating (Max)=150mA, DC Resistance (DCR) (Max)="2.2 Ohm", Operating Temperature="-55°C ~ 125°C", Package / Case="0402 (1005 Metric)", Ratings=-
FB2 FB3: library part CMP-00231-5, "FERRITE CHIP 330 OHM 1.7A 0603", Current Rating=1.7A, DC Resistance (DCR)="80 mOhm Max", Package / Case="0603 (1608 Metric)"
FD1 FD2 FD3 FD4: library part fiducial_01, "Fiducial"
FD5 FD6 FD7 FD8 FD9 FD10: library part fiducial_01_no_overlay, "Fiducial with no overlay"
FOT1 FOT2: library part CMP-1167-0000-7, "Industrial Ethernet Fiber Optic", Manufacturer=Firecomms, Voltage - Supply=3.3V
J1 J3 J8 J10: library part CMP-00332-3, "CONN TERM BLOCK 2.54MM 10POS PCB", Color=Green, Current=6A, Manufacturer="On Shore Technology Inc.", Operating Temperature="-30°C ~ 105°C", Voltage=125V
J2 J4 J6 J7 J9 J11: library part CMP-391-0001-1, "CONN HEADER FEMALE 10POS.1\" TIN", Color=Black, Manufacturer="Sullins Connector Solutions"
J5: library part CMP-00314-2, "CONN HEADER VERT 3POS 2.54MM", Color=Black, Manufacturer="Harwin Inc."
J12: library part CMP-00492-3, "CONN RCPT 60POS 0.4MM SMD GOLD", Case/Package=Metal, Package Quantity=3000
J13: library part CMP-00491-1, "CONN RCPT 70POS 0.4MM SMD GOLD", Manufacturer=Hirose
J14: library part CMP-1158-0000-1, "HEADER TERM BLOCK 3.5MM 4POS", Manufacturer="Phoenix Contact"
L1: library part CMP-00359-2, "FIXED IND 22UH 2.2A 85.8 MOHM", DC Resistance (DCR)="85.8 mOhm Max", Operating Temperature="-40°C ~ 125°C", Package / Case=Nonstandard, Q @ Freq=-, Ratings=AEC-Q200, Tolerance=±20%
L2 L3 L4 L5: library part CMP-00368-3, "FIXED IND 1UH 1A 200 MOHM SMD", Case/Size Code=0603, DC Resistance (DCR)=200mR, Inductance=1uH, Inductor Application="POWER INDUCTOR", Inductor Type="GENERAL PURPOSE INDUCTOR", Max Operating Temperature=85°C, Min Operating Temperature=-40°C, Rated Current-Max=1A, Self Resonant Frequency=125MHz, Test Frequency=1MHz, Tolerance=20%
LED1 LED2: library part CMP-00249-2, "LED GREEN CLEAR 0402 SMD", Case Code (Imperial)=0402, Case Code (Metric)=1005, Color=Green, Forward Voltage=3.3V, Lens Color=Clear, Test Current=20mA
R1 R3 R5 R7 R10 R12 R14 R16: library part CMP-00138-3, "Resistor 0402 3.3k Ohm 0.1% 1-16 Watt", Package / Case=0402, Power="0.063W, 1/16W", Resistance=3.3k, Tolerance (%)=±0.1%
R2 R4 R6 R8 R11 R13 R15 R17: library part CMP-00137-3, "Resistor 0402 4.7k Ohm 0.1% 1-16 Watt", Package / Case=0402, Power="0.063W, 1/16W", Resistance=4.7k, Tolerance (%)=±0.1%
R9: library part CMP-00107-4, "Resistor 0402 4.7k Ohm 1% 1-16 Watt", Package / Case=0402, Power="0.063W, 1/16W", Resistance=4.7k, Tolerance (%)=±1%
R18: library part CMP-00175-3, "Resistor 0603 220 Ohm 1% 1-4 Watt", Package / Case=0603, Power="0.25W, 1/4W", Resistance=220, Tolerance (%)=±1%
R19: library part CMP-00141-5, "Resistor 0402 3.3m Ohm 1% 1-16 Watt", Package / Case=0402, Power="0.063W, 1/16W", Resistance=3.3M, Tolerance (%)=±1%
R20 R24: library part CMP-00022-6, "Resistor 0402 100 Ohm 1% 1-16 Watt", Package=0402, Power="0.063W, 1/16W", Resistance=100, Tolerance=1%
R21: library part CMP-00804-1, "Resistor 0402 470k Ohm 1% 1-16 Watt", Package=0402, Power="0.063W, 1/16W", Resistance=470k, Tolerance=1%
R23 R25: library part CMP-00012-5, "Resistor 0402 1k Ohm 1% 1-16 Watt", Package=0402, Power="0.063W, 1/16W", Resistance=1k, Tolerance=1%
R26: library part CMP-00015-10, "Resistor 0402 10k Ohm 1% 1-16 Watt", Package=0402, Power="0.063W, 1/16W", Resistance=10k, Tolerance=1%
ST1 ST2 ST3 ST4: library part CMP-504-0002-4, "ROUND SPACER M3.3 STEEL 3MM", Color=-, Manufacturer="Wurth Electronics Inc"
SW1: library part CMP-00538-1, "Tactile Switch SPST-NO Top Actuated Through Hole", Manufacturer=CTS, Max Operating Temperature=85°C, Min Operating Temperature=-40°C, Operating Force=160gf
TVS1 TVS2: library part CMP-00457-4, "TVS DIODE 51VWM 82.4VC DO214AC", Capacitance @ Frequency=-, Current - Peak Pulse (10/1000µs)=4.9A, Operating Temperature="-55°C ~ 150°C (TJ)", Package / Case="DO-214AC, SMA", Power - Peak Pulse=400W, Power Line Protection=No, Supplier Device Package="SMA (DO-214AC)", Voltage - Breakdown (Min)=56.7V, Voltage - Clamping (Max) @ Ipp=82.4V, Voltage - Reverse Standoff (Typ)=51V
TVS3: library part CMP-00446-3, "TVS DIODE 5VWM 19VC SOD323F", Capacitance @ Frequency="480pF @ 1MHz", Current - Peak Pulse (10/1000µs)="47A (8/20µs)", Operating Temperature="-55°C ~ 150°C (TA)", Package / Case="SC-90, SOD-323F", Power - Peak Pulse=890W, Power Line Protection=No, Supplier Device Package=SOD-323F, Voltage - Breakdown (Min)=6.2V, Voltage - Clamping (Max) @ Ipp=19V, Voltage - Reverse Standoff (Typ)="5V (Max)"
U1: library part CMP-00789-8, "IO Micro Composite Component"
U2 U4: library part CMP-500-0004-4, "IC BUS TRANSCVR 8BIT 24QFN", Case/Package=VQFN, High Level Output Current=-32mA, Low Level Output Current=32mA, Max Operating Temperature=85°C, Max Supply Voltage=5.5V, Min Operating Temperature=-40°C, Min Supply Voltage=1.65V, Nominal Supply Current=15uA, Package Quantity=1
U3 U5: library part CMP-736-0002-1, "IC OPAMP GP 1.4MHZ RRO 14TSSOP", Current - Input Bias=70nA, Current - Output / Channel=80mA, Current - Supply=500µA, Manufacturer=STMicroelectronics, Operating Temperature="-40°C ~ 125°C", Package / Case="14-TSSOP (0.173\", 4.40mm Width)", Supplier Device Package=14-TSSOP, Voltage - Input Offset=200µV, Voltage - Supply, Single/Dual (±)="2.5 V ~ 6 V"
U7: library part CMP-631-0001-3, "Current Source Regulator  50mA 5-TSSOP", Case/Package=SOT-353, Input Current=240uA, Max Operating Temperature=150°C, Max Power Dissipation=335mW, Max Supply Voltage=75V, Min Operating Temperature=-65°C, Output Current=50mA, Package Quantity=1
U8: library part CMP-636-0002-3, "OPTOISO 3.75KV PUSH PULL 5SO", Case/Package=SO, Forward Current=2.2mA, Forward Voltage=1.5V, Input Current=6mA, Isolation Voltage=3.75kV, Max Input Current=8mA, Max Operating Temperature=105°C, Max Output Current=10mA, Max Power Dissipation=600mW, Min Operating Temperature=-40°C, Package Quantity=1500, Reverse Breakdown Voltage=5V
U9: library part CMP-452-0001-3, "IC REG BUCK 5V 1A SYNC 10TDFN", Current - Output=1A, Frequency - Switching=600kHz, Manufacturer="Maxim Integrated", Operating Temperature="-40°C ~ 125°C (TJ)", Package / Case="10-WFDFN Exposed Pad", Supplier Device Package="10-TDFN (3x2)", Voltage - Input (Max)=60V, Voltage - Input (Min)=4.5V, Voltage - Output (Max)=-, Voltage - Output (Min/Fixed)=5V

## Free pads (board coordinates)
  round 0 hole 20 unplated: 0(-150,90) 0(-150,120) 0(-150,180) 0(-150,210) 0(-150,1840) 0(-150,1870) 0(-150,1930) 0(-150,1960) 0(-149.53,150) 0(-149.53,1900) 0(90,-150) 0(90,2200) 0(120,-150) 0(120,2200) 0(150,-149.53) 0(150,2199.53) 0(180,-150) 0(180,2200) 0(210,-150) 0(210,2200) 0(1540,-150) 0(1540,2200) 0(1570,-150) 0(1570,2200) 0(1600,-149.53) 0(1600,2199.53) 0(1630,-150) 0(1630,2200) 0(1660,-150) 0(1660,2200) 0(2990,-150) 0(2990,2200) 0(3020,-150) 0(3020,2200) 0(3050,-149.53) 0(3050,2199.53) 0(3080,-150) 0(3080,2200) 0(3110,-150) 0(3110,2200) 0(3349.53,150) 0(3349.53,1900) 0(3350,90) 0(3350,120) 0(3350,180) 0(3350,210) 0(3350,1840) 0(3350,1870) 0(3350,1930) 0(3350,1960)
  round 124.02 hole 125 unplated: H(-550,-550) H(-550,2600) H(3750,-550) H(3750,2600)

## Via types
v1: diameter 22, hole 12, Top Layer to Bottom Layer, tented both sides, 314 vias

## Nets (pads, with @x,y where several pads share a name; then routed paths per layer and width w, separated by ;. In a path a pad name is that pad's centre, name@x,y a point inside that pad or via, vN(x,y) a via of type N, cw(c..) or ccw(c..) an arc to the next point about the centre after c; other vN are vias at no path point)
3V3: C14.2 C19.2 C24.1 C34.2 C63.2 C68.2 C74.2 C79.2 J5.3 J6.9 J7.9 J12.33 J12.37 J12.51 J12.53 J12.55 J12.57 J12.59 L2.1 L3.1 L4.1 L5.1 LED1.A LED2.A R9.1 R26.2 U1.B33 U1.B37 U1.B51 U1.B53 U1.B55 U1.B57 U1.B59 U2.1 U2.2 U4.1 U4.2 U8.6 | length 2381.6
  Top Layer w6: LED1.A@-75.32,530 v1(-55,530) ; LED2.A@-70.32,1800 v1(-50,1800) ; U1.B37@1179.65,969.88 1201.44,969.88 1218.26,953.06 1226.94,953.06 v1(1230,950) ; U1.B33@1179.65,1001.38 1180.33,1000.69 1219.31,1000.69 v1(1220,1000)
  Top Layer w10: v1(840,1720) R26.2@840,1749.82 ; U1.B59@1180.63,796.65 v1@1219.65,796.65 ; U1.B57@1180.63,812.4 v1@1219.65,812.4 ; U1.B55@1180.63,828.15 v1@1219.65,828.15 ; U1.B53@1180.63,843.9 1219.65,843.9 ; U1.B51@1180.63,859.65 v1@1219.65,859.65 ; U8.6@1347.17,1620 1347.32,1619.84 1424.84,1619.84 C24.1@1425,1619.69 1429.69,1615 1429.69,1616.75 1429.84,1616.91 1449.84,1616.91 1457.7,1609.05 1457.7,1592.3 v1(1460,1590) ; U2.2@1683.58,517.91 1712.09,517.91 1719.69,510.31 C14.2@1750,510.31 ; U2.1@1702.28,479.53 1743.67,479.53 1750,485.86 C14.2@1750,510.31 ; v1(1779.69,510.31) C14.2@1750,510.31 ; v1(2030,475) 2030,360.18 R9.1@2040,350.18 ; U4.2@2413.58,472.91 2414.09,473.43 2414.09,499.09 2430,515 C19.2@2479.1,515 ; U4.1@2432.28,434.53 2464.53,434.53 2479.1,449.1 C19.2@2479.1,515 ; v1(2480.31,547.88) C19.2@2480.31,515 C19.2@2479.1,515
  Top Layer w25: C34.2@3035,516.42 3036.79,518.21 3128.21,518.21 J6.9@3130,520 ; J6.9@3130,518.21 3253.21,518.21 J7.9@3255,520
  Top Layer w30: L3.1@465,902.56 465,900.12 465.75,899.37 508.07,899.37 ; L2.1@520,1047.56 570,1047.56 573.03,1044.53 C68.2@575,1044.53 575.75,1043.78 610.28,1043.78 v1(613.69,1040.36) ; C63.2@520.47,880 521.03,880.56 v1(521.03,910.05) 521.03,894.93 C63.2@520.47,894.37 ; L5.1@602.56,1445 v1(688.3,1445) ; L4.1@602.56,1550 602.8,1550.24 C74.2@654.76,1550.24 ; C74.2@655,1550.47 v1(691.75,1550.47)
  Bottom Layer w25: v1(2542.23,583.57) 2547.8,583.57 2576.87,554.49 v1(2577.27,554.49) 2577.27,554.1 v1(2611.38,520) J6.9@3130,520 J7.9@3255,520
  other v1: 1215,755 1240,755 1265,755 1215,780 1240,780 1265,780 1215,805 1240,805 1265,805 1215,830 1240,830 1265,830 1215,855 1240,855 1265,855
5V: C4.2 C5.1 C28.2 C29.+ FB1.1 J5.1 J12.52 J12.54 J12.56 J12.58 J12.60 L1.2 U1.B52 U1.B54 U1.B56 U1.B58 U1.B60 U9.5 | length 2898.3
  Top Layer w10: v1(830,620) v1@830,630 ; v1(885,378.73) 885.32,379.05 910.71,379.05 U9.5@911.02,379.36 ; 1019.72,797.01 U1.B60@1058.74,797.01 ; 1019.72,812.76 U1.B58@1058.74,812.76 ; 1019.72,828.5 U1.B56@1058.74,828.5 ; 1019.72,844.25 U1.B54@1058.74,844.25 ; 1019.72,860 U1.B52@1058.74,860
  Top Layer w20: v1(2920,1296.61) C4.2@2885,1296.61 2879.69,1301.92 C5.1@2879.69,1355 2882.85,1358.17 FB1.1@2920,1358.17
  Bottom Layer w10: v1(830,620) 830,433.73 v1(885,378.73)
  Bottom Layer w40: 980,860 1135,860 1167,892 1500,892 1580,972 1580,1080 1895,1395 2615,1395 2713.39,1296.61 v1(2920,1296.61)
  other v1: 980,725 1005,725 980,750 1005,750 980,775 1005,775 980,800 1005,800 855,805 880,805 905,805 930,805 955,805 980,825 1005,825 855,830 880,830 905,830 930,830 955,830
5VA: C3.1 C6.2 C7.1 C17.1 FB1.2 U3.4 U5.4 | length 340.2
  Top Layer w10: U3.4@2446.14,1660 2489.09,1660 C17.1@2495,1654.09 2495,1670 v1(2505,1680) ; U5.4@2836.14,1660 2899.69,1660 C3.1@2900,1659.69 2900,1680 v1(2910,1690)
  Top Layer w20: C7.1@2882.03,1398.52 FB1.2@2920,1398.52 2915,1403.52 2915,1435.57 2914.96,1435.61 2914.96,1474.39 2915,1474.43 2915,1511.27 2920,1516.27 v1(2920,1516.81)
A1: J1.1 J2.1 U5.3 | length 536.8
  Top Layer w6: U5.3@2836.14,1634.41 2879.41,1634.41 2885,1640 2912.73,1640 2930,1657.27 2930,1746.72 2880,1796.72 J2.1@2880,1880
  Top Layer w10: J2.1@2880,1880 J1.1@2880,2070
A2: J1.2 J2.2 U5.5 | length 489.3
  Top Layer w6: J2.2@2780,1880 2780,1825 2820,1785 2850,1785 2885,1750 2885,1695 2875,1685 2836.73,1685 U5.5@2836.14,1685.59
  Top Layer w10: J2.2@2780,1880 J1.2@2780,2070
A3: J1.3 J2.3 U5.10 | length 494.2
  Top Layer w6: U5.10@2603.86,1685.59 2569.41,1685.59 2560,1695 2560,1742.06 2602.94,1785 2640,1785 2680,1825 J2.3@2680,1880
  Top Layer w10: J2.3@2680,1880 J1.3@2680,2070
A4: J1.4 J2.4 U5.12 | length 506.9
  Top Layer w6: J2.4@2580,1880 2580,1810 2540,1770 2540,1650 2555.59,1634.41 U5.12@2603.86,1634.41
  Top Layer w10: J2.4@2580,1880 J1.4@2580,2070
A5: J1.5 J2.5 U3.3 | length 524
  Top Layer w6: U3.3@2446.14,1634.41 2509.41,1634.41 2525,1650 2525,1765 2480,1810 J2.5@2480,1880
  Top Layer w10: J2.5@2480,1880 J1.5@2480,2070
A6: J1.6 J2.6 U3.5 | length 497.6
  Top Layer w6: J2.6@2380,1880 2380,1820 2410,1790 2460,1790 2490,1760 2490,1695 2480.59,1685.59 U3.5@2446.14,1685.59
  Top Layer w10: J2.6@2380,1880 J1.6@2380,2070
A7: J1.7 J2.7 U3.10 | length 483.5
  Top Layer w6: U3.10@2213.86,1685.59 2179.41,1685.59 2175,1690 2175,1755 2201,1781 2234,1781 2280,1827 J2.7@2280,1880
  Top Layer w10: J2.7@2280,1880 J1.7@2280,2070
A8: J1.8 J2.8 U3.12 | length 489
  Top Layer w6: J2.8@2180,1880 2180,1817 2156,1793 2156,1659 2180.59,1634.41 U3.12@2213.86,1634.41
  Top Layer w10: J2.8@2180,1880 J1.8@2180,2070
E1: J8.1 J9.1 U2.14 | length 1283.3
  Top Layer w6: J9.1@950,170 J9.1@950,180 ; v1(1480,290) 1480,322.66 1506.42,349.08 U2.14@1506.42,382.09
  Top Layer w10: J8.1@950,-20 J9.1@950,170
  Bottom Layer w6: J9.1@950,170 950,166.49 976.09,140.41 979.59,140.41 1057,63 1433.91,63 1501,130.09 1501,209.91 1480,230.91 v1(1480,290)
  Bottom Layer w10: J8.1@950,-20 J9.1@950,166.49
E2: J8.2 J9.2 U2.15 | length 1001.3
  Top Layer w6: J8.2@1050,-20 J9.2@1050,170 J9.2@1050,180 ; v1(1511.63,326.01) 1526.1,340.48 U2.15@1526.1,382.09
  Bottom Layer w6: J9.2@1050,170 1050,166.49 1076.09,140.41 1079.59,140.41 1135,85 1438.94,85 1489,135.06 1489,204.94 1468,225.94 1468,265.28 1459.09,274.19 1459.09,302.75 1482.36,326.01 v1(1511.63,326.01)
E3: J8.3 J9.3 U2.16 | length 830.5
  Top Layer w6: J8.3@1150,-20 J9.3@1150,170 J9.3@1150,180 ; v1(1440,265) 1483.28,265 1493.74,275.45 1511.92,275.45 1545.79,309.32 U2.16@1545.79,382.09
  Bottom Layer w6: J9.3@1150,170 1172,148 1197,148 1245,100 1353.94,100 1395,141.06 1395,188.94 1440,233.94 v1(1440,265)
E4: J8.4 J9.4 U2.17 | length 640.2
  Top Layer w6: J9.4@1250,170 1250,180 1315,245 1481.06,245 1499.51,263.45 1516.9,263.45 1565.47,312.03 U2.17@1565.47,382.09
  Top Layer w10: J8.4@1250,-20 J9.4@1250,170
E5: J8.5 J9.5 U2.18 | length 559.7
  Top Layer w6: J9.5@1350,170 1388.36,170 1411,192.64 1411,204.94 1439.06,233 1486.03,233 1504.48,251.45 1521.87,251.45 1585.16,314.75 U2.18@1585.16,382.09
  Top Layer w10: J8.5@1350,-20 J9.5@1350,170
E6: J8.6 J9.6 U2.19 | length 476.4
  Top Layer w6: J9.6@1450,170 1450,180 1509.45,239.45 1526.84,239.45 1604.84,317.46 U2.19@1604.84,382.09
  Top Layer w10: J8.6@1450,-20 J9.6@1450,170
E7: J8.7 J9.7 U2.20 | length 446
  Top Layer w6: J9.7@1550,170 J9.7@1550,180 ; J9.7@1562,162 1562,192 1624.53,254.53 U2.20@1624.53,382.09
  Top Layer w10: J8.7@1550,-20 J9.7@1550,170
E8: J8.8 J9.8 U2.21 | length 396.3
  Top Layer w6: J9.8@1644.21,175.79 U2.21@1644.21,382.09
  Top Layer w10: J8.8@1650,-20 J9.8@1650,170
ESTOP_IN: J12.30 U1.B30 U8.5 | length 1033.5
  Top Layer w6: v1(1010,1000) 1041.87,1031.87 1058.37,1031.87 U1.B30@1059.37,1032.87 ; v1(1060,1450) 1140,1450 1260,1570 U8.5@1347.17,1570
  Bottom Layer w6: v1(1010,1000) 1006.94,996.94 995.22,996.94 993.28,995 944.75,995 868,1071.75 868,1099.72 1060,1291.72 v1(1060,1450)
F1: J10.1 J11.1 U4.14 | length 522.2
  Top Layer w6: J11.1@1980,170 2004,194 2019,194 2124.45,299.45 2210,299.45 2236.42,325.87 U4.14@2236.42,337.09
  Top Layer w10: J10.1@1980,-20 J11.1@1980,170
F2: J10.2 J11.2 U4.15 | length 450.5
  Top Layer w6: J11.2@2080,170 2080,180 2092,192 2127,192 2253.59,318.59 2253.59,334.57 U4.15@2256.1,337.09
  Top Layer w10: J10.2@2080,-20 J11.2@2080,170
F3: J10.3 J11.3 U4.16 | length 396.8
  Top Layer w6: J11.3@2180,170 2194,184 2194,219 2275.79,300.79 U4.16@2275.79,337.09
  Top Layer w10: J10.3@2180,-20 J11.3@2180,170
F4: J10.4 J11.4 U4.17 | length 363.5
  Top Layer w6: J11.4@2280,170 2293.74,183.74 2293.74,335.35 U4.17@2295.47,337.09
  Top Layer w10: J10.4@2280,-20 J11.4@2280,170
